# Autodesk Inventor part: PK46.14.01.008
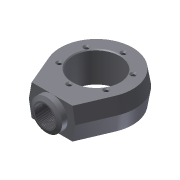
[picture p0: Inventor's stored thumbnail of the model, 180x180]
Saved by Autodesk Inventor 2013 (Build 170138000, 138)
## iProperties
Shininess: 64.0
Angle Display Precision: 2
Document Length Units: 11269
Document Angle Units: 11279
Document Time Units: 11290
Document Mass Units: 11283
Document Length Units Precision: 3
Document Angle Units Precision: 2
Created: 2003-06
Part Number: PK46.14.01.008
Material: Steel, Mild
Description: Проушина
Document SubType Name: Modeling
Designer: Ситников
Density: 1 g/cm^3
Density: 0.0
Volumn: 0.0
Area: 0.0
PropertySet Name: Model Information
Control State: 0
Master: False
Checked Out: True
Checked Out Date: 2008-10-15
Last Check In Date: 2008-10-15
Title: Проушина
Author: Ситников
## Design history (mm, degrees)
body "Solid1"
sketch "Sketch1"
  geometry: L1 (-69.05, -29.276)-(-45, -86); L2 (-45, -86)-(45, -86); L3 (45, -86)-(69.05, -29.276); A1 r 75 centre (0, 0) between (69.05, -29.276) and (-69.05, -29.276)
  constraints: 6 end point, 2 point on circle, 2 tangent, 1 centre point, 1 horizontal, 1 other
  dimensions: "d0" = 150 diameter of A1; "d1" = 86 distance from line of A1.centre L2; "d2" = 90 distance of L1.end L2.end; "d3" = 45 horizontal distance of A1.centre L1.end
sketch "Sketch5"
  geometry: C1 r 22.5 at (0, 0) reference
sketch "Sketch6"
  geometry: C1 r 19.918 at (0, 0) reference
sketch "Sketch2"
  geometry: L1 (39.569, -30)-(-39.569, -30) reference; L2 (-70, 30)-(70, 30) reference; L3 (0, 30)-(0, -30); L4 (-45, 0)-(45, 0); C1 r 30 at (0, 0); 2 further points
  constraints: 4 end point, 3 midpoint, 1 centre point, 1 perpendicular
  dimensions: "d10" = 60 diameter of C1
sketch "Sketch3"
  geometry: A1 r 70 centre (0, 0) between (64.447, -27.324) and (-64.447, -27.324) reference
sketch "Sketch4" dims "d24" = 105
  geometry: L1 (39.569, -86)-(0, -86) reference; L2 (0, 0)-(0, 52.5); C1 r 46.6 at (0, 0) reference
  constraints: 2 end point, 1 coincident, 1 perpendicular, 1 vertical alignment, 2 other
extrude "Extrusion1" new body sketch "Sketch1" stored distance "d4" = 60; taper "d5" = 0 deg
chamfer "Chamfer1" distance "d6" = 5; stored, may be unused: second distance "d7" = 30, angle "d51" = 45 deg
chamfer "Chamfer2" distance "d8" = 5; stored, may be unused: second distance "d9" = 30, angle "d52" = 45 deg
extrude "Extrusion2" join sketch "Sketch2" distance "d11" = 14; taper "d12" = 0 deg
chamfer "Chamfer3" distance "d13" = 7.5; stored, may be unused: angle "d14" = 25 deg, second distance "d53" = 7.5
hole "Hole1" sketch "Sketch3" diameter "d15" = 90; stored, may be unused: countersink angle "d19" = 82 deg, drill point angle "d21" = 118 deg; dims "d16" = 6, "d17" = 4, "d18" = 2, "d20" = 8
chamfer "Chamfer4" distance "d22" = 1.6; stored, may be unused: second distance "d23" = 1.6, angle "d54" = 45 deg
hole "Hole2" sketch "Sketch4" diameter "d25" = 6.647; stored, may be unused: countersink angle "d29" = 82 deg, drill point angle "d31" = 118 deg; dims "d26" = 18, "d27" = 11.2, "d28" = 2, "d30" = 23
pattern_circular "Circular Pattern1" dims angle "d34" = 360 deg
mirror "Mirror1"
hole "Hole3" sketch "Sketch5" diameter "d35" = 39.835; stored, may be unused: countersink angle "d39" = 82 deg, drill point angle "d41" = 0 deg; dims "d36" = 31.5, "d37" = 11.2, "d38" = 2, "d40" = 31.5
hole "Hole4" sketch "Sketch6" diameter "d42" = 43; stored, may be unused: countersink angle "d46" = 82 deg, drill point angle "d48" = 0 deg; dims "d43" = 31.5, "d44" = 11.2, "d45" = 2, "d47" = 8.5
chamfer "Chamfer5" distance "d49" = 0.5; stored, may be unused: second distance "d50" = 0.5, angle "d55" = 45 deg
